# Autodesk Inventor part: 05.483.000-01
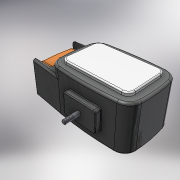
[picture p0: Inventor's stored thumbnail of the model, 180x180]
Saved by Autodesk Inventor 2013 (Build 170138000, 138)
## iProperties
Created: 2005-07
Part Number: 05.483.000-01
Material: Steel, Mild
Document SubType Name: Modeling
Designer: PVitaliy
Manufacturer: Standard
Standards Organization: Custom
Density: 7.86 g/cm^3
Author: PVitaliy
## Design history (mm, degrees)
derived "05.483.000.ipt"
body "Solid1"
tag "TaggingFeature2"
feature "Solid1::05.483.000.ipt" dims "d0" = 10
